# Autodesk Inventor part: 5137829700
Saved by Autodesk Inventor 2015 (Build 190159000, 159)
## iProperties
Created: 2020-07
Part Number: 5137829700
Checked By: TraceParts S.A.
Material: Generic
Catalog Web Link: www.traceparts.com
Document SubType Name: Modeling
Designer: TraceParts
Density: 1 g/cm^3
Appearance: Default
Company: TraceParts S.A.
Author: TraceParts
REFERENCE: 5137829700
DESIGN: CVAB-2000/315 N ECOWATT 0,21KW (230V 50/60HZ) N8 - 5137829700
SUPPLIER: Soler & Palau
TraceParts.PartNumber: 10-20122018-119636
TraceParts.PartTitle: CVAB/T-N_ECO
TraceParts.InstanceId: 10-20122018-1196363MWTLO9GDKNFLTOAVE8T2C6TQ
TraceParts.PartStatus: Published
TraceParts.PartVersion: 1.0.2
TRACEPARTS: TRACEPARTS
TraceParts.PartLanguage: en
TraceParts.ClassPath: SOLER_PALAU:10-20122018-119636
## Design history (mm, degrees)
feature "5137829700"
body "Solid1"
